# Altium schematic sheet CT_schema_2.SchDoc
size 294 x 169 mm
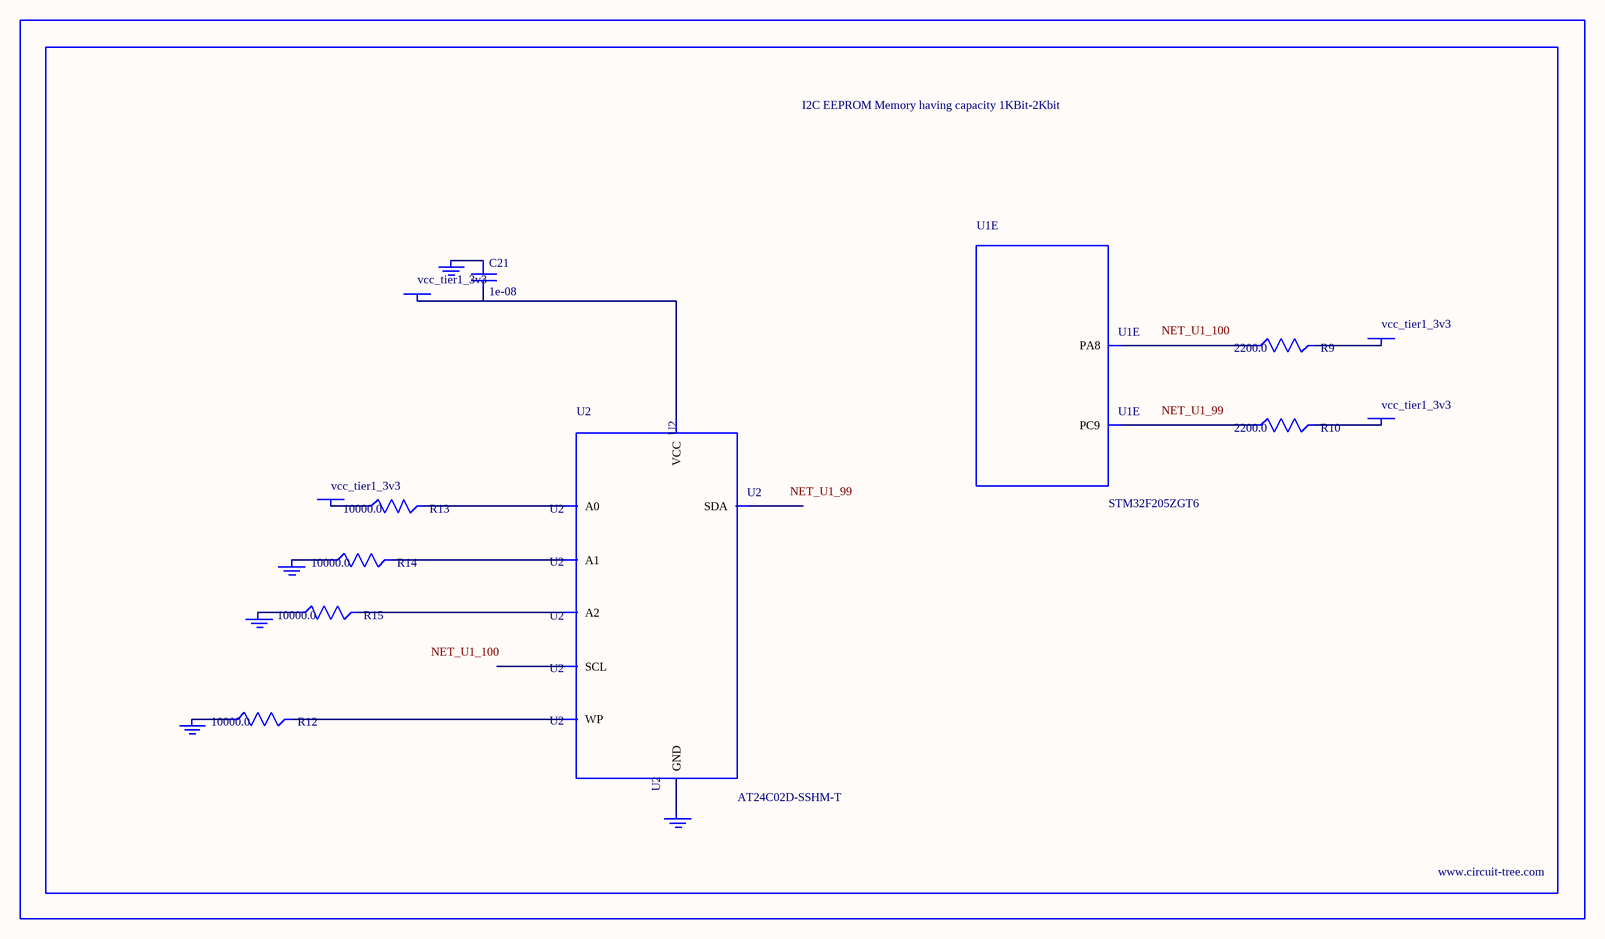
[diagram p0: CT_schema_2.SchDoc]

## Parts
BORDER1  (no value)
C21  1e-08  [C0402]
GND_INSTANCE_1_0  (no value)
GND_INSTANCE_1_1  (no value)
GND_INSTANCE_1_2  (no value)
GND_INSTANCE_1_3  (no value)
GND_INSTANCE_1_4  (no value)
POWER_INSTANCE_1_0  vcc_tier1_3v3
POWER_INSTANCE_1_1  vcc_tier1_3v3
POWER_INSTANCE_1_2  vcc_tier1_3v3
POWER_INSTANCE_1_3  vcc_tier1_3v3
R9  2200.0  [R0603]
R10  2200.0  [R0603]
R12  10000.0  [R0603]
R13  10000.0  [R0603]
R14  10000.0  [R0603]
R15  10000.0  [R0603]
U1  STM32F205ZGT6  [LQFP144]  (part E of 12)
U2  AT24C02D-SSHM-T  [AT24C02D]

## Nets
NetC21_1: C21.1 GND_INSTANCE_1_3.0(GND)
NetC21_2: C21.2 POWER_INSTANCE_1_1.0(PWR) U2.8(VCC)
NetGND_INSTANCE_1_0_0: GND_INSTANCE_1_0.0(GND) R14.1
NetGND_INSTANCE_1_1_0: GND_INSTANCE_1_1.0(GND) R15.1
NetGND_INSTANCE_1_2_0: GND_INSTANCE_1_2.0(GND) R12.1
NetGND_INSTANCE_1_4_0: GND_INSTANCE_1_4.0(GND) U2.4(GND)
NetPOWER_INSTANCE_1_0_0: POWER_INSTANCE_1_0.0(PWR) R13.1
NetPOWER_INSTANCE_1_2_0: POWER_INSTANCE_1_2.0(PWR) R10.2
NetPOWER_INSTANCE_1_3_0: POWER_INSTANCE_1_3.0(PWR) R9.2
NetR9_1: R9.1 U1.100(PA8)
NetR10_1: R10.1 U1.99(PC9)
NetR12_2: R12.2 U2.7(WP)
NetR13_2: R13.2 U2.1(A0)
NetR14_2: R14.2 U2.2(A1)
NetR15_2: R15.2 U2.3(A2)

Not connected (* = marked no-connect by the designer): U2 5(SDA) 6(SCL)

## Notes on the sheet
- Labels drawn without touching a wire or pin: NET_U1_99, NET_U1_100

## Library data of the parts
BORDER1 = BORDER_PAGE1
C21 = C0402C103K3RAC
GND_INSTANCE_1_0-GND_INSTANCE_1_4 = GND
POWER_INSTANCE_1_0-POWER_INSTANCE_1_3 = PWR
R9 R10 = RC0603JR-072K2L
R12-R15 = RC0603JR-0710KL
